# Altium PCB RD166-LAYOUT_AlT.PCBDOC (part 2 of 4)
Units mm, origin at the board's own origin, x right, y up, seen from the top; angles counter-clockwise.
Board outline 88.7 x 59.07 mm, 2 copper layers (TOP, BOTTOM), stack 0 mm thick; 138 components, 120 nets, 706 pads, 0 vias.
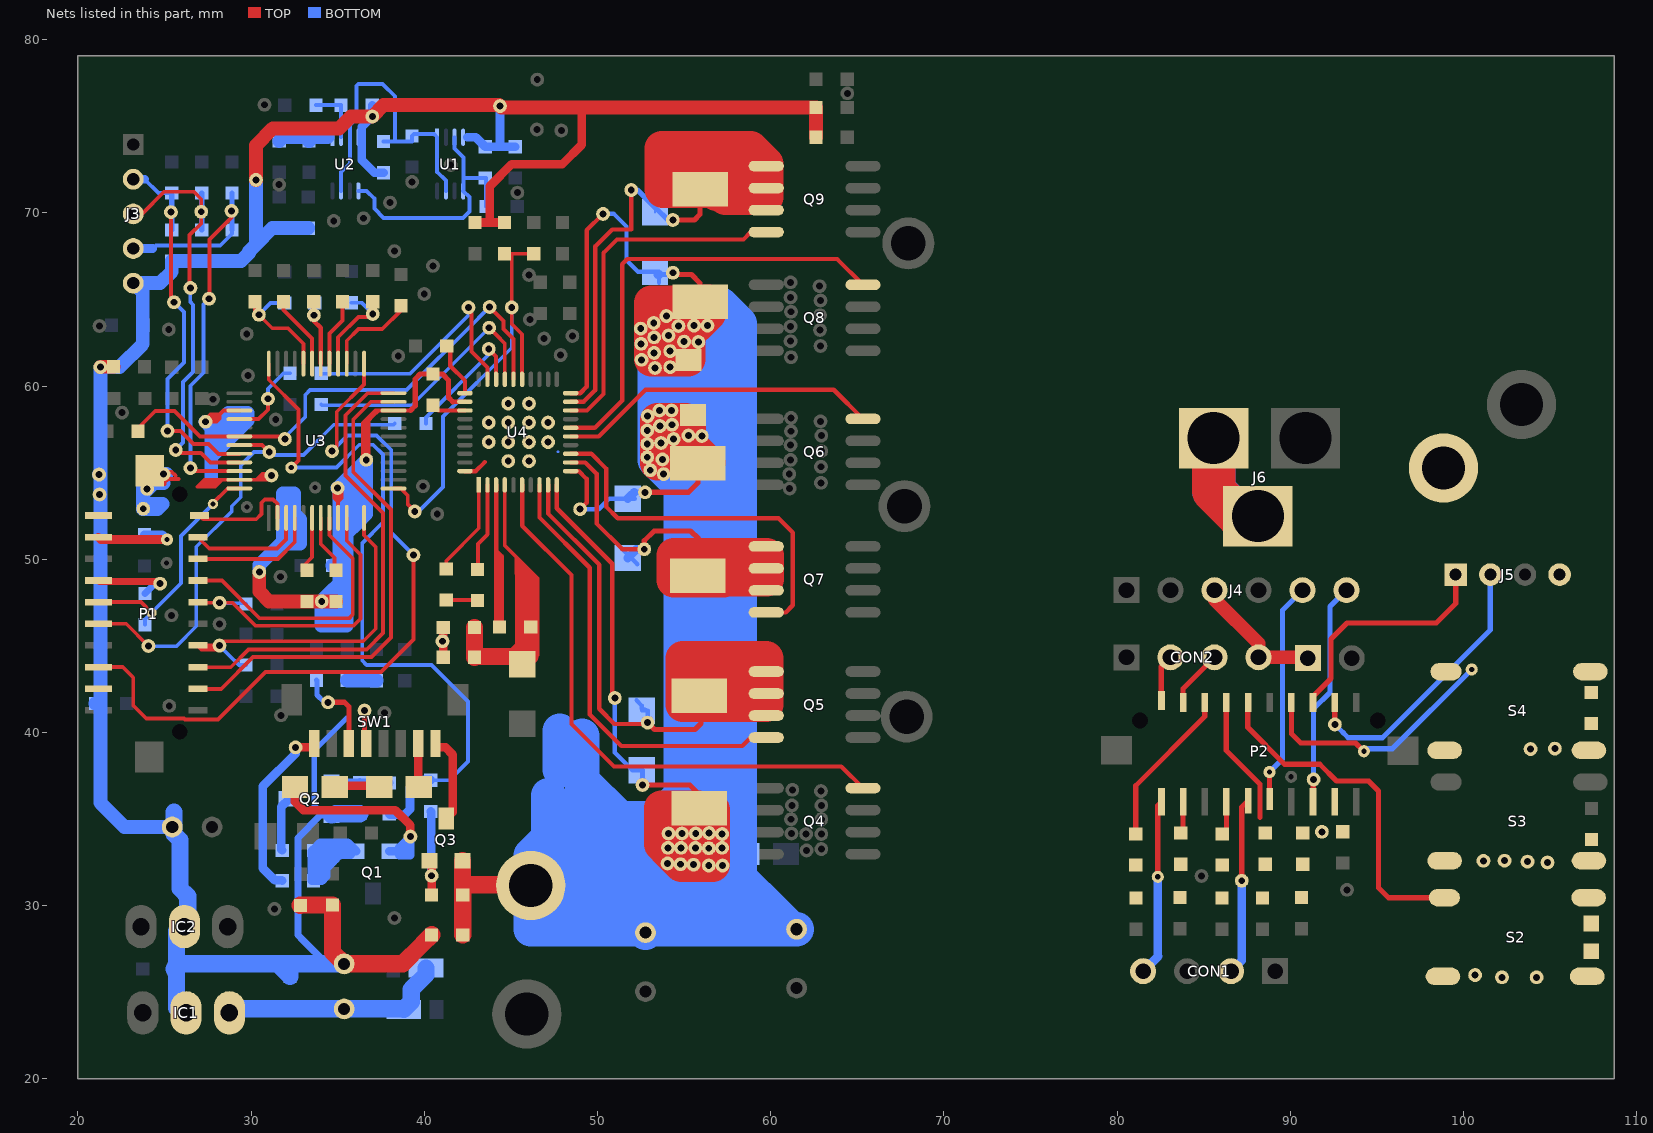
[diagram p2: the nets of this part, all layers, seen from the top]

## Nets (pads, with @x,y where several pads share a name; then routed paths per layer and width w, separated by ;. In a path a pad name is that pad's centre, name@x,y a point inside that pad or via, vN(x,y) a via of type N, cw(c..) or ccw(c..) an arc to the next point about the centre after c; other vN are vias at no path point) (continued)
GND: C3.2 C4.2 C5.2 C6.2 C9.2 C10.2 C11.2 C12.2 C13.2 C14.1 C15.2 C16.1 C17.2 C18.2 C19.2 C20.2 C21.2 C23.2 C27.2 C28.2 C29.2 C30.2 C34.2 IC1.2 IC2.2 J3.5 NTC1.1 P1.10 P1.22 pad.@21.3,61.091 pad.@21.25,53.741 pad.@21.225,54.891 pad.@23.775,52.916 pad.@24,54.066 pad.@24.95,54.916 pad.@27.375,57.941 pad.@30.287,71.903 pad.@30.476,49.265 pad.@31.176,54.84 pad.@34.084,47.565 pad.@35,54.116 pad.@36.65,55.743 pad.@36.551,41.265 pad.@37,75.566 pad.@44.375,76.166 Q2.E R5.1 R9.2 R11.1 R15.1 R18.2 R20.2 SW1.4 U1.4 U2.4 U3.9 U3.22 U3.39 U3.47 U4.32 | length 281.5
  TOP w0.22: P1.22@24.651,54.34 25.001,54.34 ; P1.22@24.901,54.39 24.951,54.39 25.201,54.64 25.826,54.64 ; pad.@25.038,54.828 pad.@24.95,54.916 25.076,55.04 25.426,55.04 25.638,54.828 ; U3.47@29.325,54.591 28.326,54.59 ; U3.39@29.325,58.591 28.401,58.59 28.176,58.365 ; U3.47@29.326,54.59 30.301,54.59 ; pad.@35.001,54.115 pad.@35.026,54.115 ; U3.9@35.026,52.392 35.026,53.34 ; pad.@36.65,55.743 36.776,55.869 36.776,58.015 37.03,58.269 ; pad.@36.65,55.743 pad.@36.601,55.793 ; 37.352,58.591 U3.22@38.225,58.591 ; U3.22@38.225,58.591 39.201,58.59 ; 27.101,54.39 28.126,54.39 ; 27.101,54.39 26.901,54.19 27.926,54.19 28.126,54.39 ; 27.101,54.39 27.301,54.59 28.326,54.59 ; pad.@27.376,57.942 pad.@27.375,57.941 pad.@27.476,57.94 ; pad.@27.376,57.942 27.376,58.09 27.651,58.365 ; pad.@27.376,57.942 27.651,58.217 27.651,58.365 ; pad.@27.476,57.94 pad.@27.751,57.94 ; pad.@27.476,57.94 27.901,58.365 ; 27.651,58.365 27.901,58.365 ; pad.@27.751,57.94 28.176,58.365 ; pad.@27.751,57.94 28.001,57.94 28.176,58.115 28.176,58.365 ; 27.901,58.365 28.176,58.365 ; 28.126,54.39 28.326,54.59 ; 30.301,54.59 30.501,54.79 ; 30.301,54.59 pad.@30.926,54.59 ; 30.501,54.79 pad.@31.126,54.79 ; 30.501,54.79 30.651,54.94 31.076,54.94 pad.@31.176,54.84 pad.@31.126,54.79 ; pad.@30.926,54.59 pad.@31.126,54.79 ; pad.@30.926,54.59 pad.@31.126,54.79 ; 35.026,53.34 pad.@35.026,54.115 ; 35.026,53.34 34.826,53.54 34.826,53.915 pad.@35.026,54.115 ; 35.026,53.34 35.226,53.54 35.226,53.915 pad.@35.026,54.115 ; pad.@36.601,55.793 36.451,55.943 36.451,57.865 36.601,58.015 ; pad.@36.601,55.793 36.601,58.015 ; 36.601,58.015 37.176,58.59 37.351,58.59 ; 37.03,58.269 37.351,58.59 ; 37.03,58.269 37.351,58.59
  TOP w0.25: 41.65,59.091 U4.32@42.35,59.091
  TOP w0.3: pad.@36.551,41.265 36.551,39.465 SW1.4@36.65,39.366 ; 39.201,58.59 39.476,58.865 39.476,60.415 39.751,60.69 C34.2@40.5,60.691 ; C34.2@40.5,60.691 41.051,60.69 41.401,60.34 41.401,59.34 41.65,59.091
  TOP w0.5: C29.2@42.925,69.441 43.776,69.44 ; C30.2@44.625,69.441 43.776,69.44 ; 49.101,76.09 49.101,73.94 47.976,72.815 45.051,72.815 43.776,71.54 43.776,69.44
  TOP w0.8: pad.@21.3,61.091 21.325,61.116 R11.1@22.05,61.116 ; pad.@30.287,71.903 30.279,71.912 30.279,73.895 31.249,74.865 35.076,74.865 35.777,75.566 pad.@37,75.566 37.656,76.222 44.319,76.222 pad.@44.375,76.166 44.451,76.09 49.101,76.09 62.625,76.09 NTC1.1@62.625,74.366 ; pad.@30.476,49.265 30.476,48.132 31.042,47.566 C27.2@33.225,47.566 33.226,47.565 pad.@34.084,47.565 34.084,47.566 C28.2@34.9,47.566
  TOP w1: R15.1@32.85,30.016 32.875,30.041 C12.2@34.7,30.041 34.701,30.04 34.701,27.315 ; C3.2@35.376,26.64 38.751,26.64 39.872,27.761 ; 39.872,27.763 R9.2@40.425,28.316 ; 34.701,27.315 C3.2@35.375,26.641 ; 34.701,27.315 C3.2@35.375,26.641 ; 34.701,27.315 C3.2@35.375,26.641
  BOTTOM w0.127: 29.269,58.446 29.275,58.441
  BOTTOM w0.3: Q2.E@34.232,35.234 33.65,35.816 33.65,38.966 35.525,40.841
  BOTTOM w0.4: 33.012,28.004 34.375,26.641 ; Q2.E@34.649,35.234 34.232,35.234 34.018,35.234 32.7,33.916 32.7,28.316 33.012,28.004 34.375,26.641 ; C3.2@35.375,26.916 C3.2@35.375,26.641 34.375,26.641
  BOTTOM w0.5: R20.2@37,76.216 pad.@37,75.566 36.4,74.966 36.4,73.041 37.125,72.316 C15.2@37.65,72.316 ; 42.476,74.366 42.975,74.366 R18.2@43.525,73.816 44.375,73.816 ; pad.@44.375,76.166 44.375,73.816 ; C14.1@45.25,73.816 44.375,73.816
  BOTTOM w0.8: C9.2@21.025,41.666 21.027,41.664 C9.2@21.3,41.664 ; pad.@21.25,54.866 pad.@21.225,54.891 pad.@21.3,54.966 ; pad.@24,54.066 pad.@24.038,54.028 ; 24.95,54.391 24.4,54.391 pad.@24.038,54.028 ; pad.@25.125,54.916 23.75,54.916 23.75,53.741 ; C6.2@25.45,34.541 22.7,34.541 21.3,35.941 C9.2@21.3,41.664 ; pad.@27.375,57.941 27.7,57.616 ; 27.7,54.641 27.7,55.916 ; pad.@30.287,71.903 30.287,68.178 ; pad.@30.476,49.265 30.475,49.666 31.725,50.916 32.325,50.916 ; 31.85,51.041 31.85,53.791 32.475,53.791 32.475,52.651 32.825,52.301 32.825,50.916 32.325,50.916 ; 32.325,52.501 32.325,50.916 ; C16.1@33.3,69.116 C17.2@31.625,69.116 31.225,69.116 30.287,68.178 ; 34.775,48.091 34.775,46.166 ; 35.515,54.351 35.515,51.481 ; C11.2@35.55,43.016 35.575,42.991 C10.2@37.25,42.991 ; 36.137,54.903 36.137,52.103 ; C9.2@21.3,41.664 21.3,54.891 pad.@21.3,54.966 ; pad.@21.3,54.966 pad.@21.3,61.091 22.4,61.091 23.75,62.441 C18.2@23.75,63.516 23.75,63.518 23.75,65.391 ; J3.5@23.74,65.941 24.75,65.941 25.425,66.616 C21.2@25.425,67.216 C20.2@27.15,67.216 C19.2@28.9,67.216 29.425,67.216 29.881,67.672 29.881,67.772 30.287,68.178 ; J3.5@23.74,65.941 J3.5@23.2,65.941 23.75,65.391 ; J3.5@23.74,65.941 23.75,65.931 23.75,65.391 ; pad.@23.75,52.891 23.75,53.741 ; pad.@23.75,52.891 24.6,52.891 24.9,53.191 24.05,53.191 pad.@23.775,52.916 pad.@23.75,52.891 ; 23.75,53.741 pad.@24.038,54.028 ; 27.7,55.916 27.7,56.866 ; 27.7,55.916 29.8,58.016 29.8,58.441 29.275,58.441 ; 27.7,56.866 27.7,57.616 ; 27.7,56.866 29.275,58.441 ; 27.7,57.616 27.875,57.616 28.7,58.441 29.275,58.441 ; pad.@34.05,47.532 34.05,47.566 34.066,47.582 34.525,48.041 ; pad.@34.05,47.532 34.05,46.176 34.06,46.166 34.775,46.166 ; pad.@34.05,47.532 pad.@34.084,47.565 34.525,48.007 34.525,48.041 ; 34.525,48.041 35.093,48.609 35.093,49.641 35.093,54.023 35,54.116 35.022,54.116 pad.@36.65,55.743 36.65,52.616 36.137,52.103 ; 34.775,46.166 35.515,46.166 35.515,51.481 ; 35.515,51.481 36.137,52.103
  BOTTOM w0.801: C23.2@34.7,49.641 35.093,49.641
  BOTTOM w1: C6.2@25.45,34.541 C6.2@25.55,34.541 ; C5.2@25.55,26.342 C5.2@25.55,26.341 C5.2@25.7,26.491 ; 25.55,35.391 C6.2@25.55,34.541 ; IC2.2@26.15,28.791 IC2.2@26.375,29.216 ; IC1.2@26.25,23.816 26.025,23.766 25.7,24.091 C5.2@25.7,26.491 ; 31.675,26.491 C4.2@32.249,25.917 ; C4.2@32.249,25.916 C4.2@32.249,25.917 ; C4.2@32.25,25.916 C4.2@32.249,25.917 ; Q2.E@34.65,35.234 34.897,35.316 R5.1@36.275,35.316 ; C3.2@35.375,26.641 34.375,26.641 32.249,26.641 ; C6.2@25.55,34.541 25.55,34.141 25.9,33.791 25.9,30.991 26.35,30.541 26.35,29.241 IC2.2@26.375,29.216 ; C5.2@25.7,26.491 25.7,28.541 26.05,28.891 IC2.2@26.375,29.216 ; C5.2@25.7,26.491 25.85,26.641 32.249,26.641 ; C4.2@32.249,25.917 32.249,26.641
GND1: BOOT1.1 C43.1 C44.2 C45.2 C46.2 CON1.4 CON2.4 J4.3 J5.4 P2.10 pad.@82.351,31.665 pad.@91.823,34.266 pad.@100.675,25.991 pad.@101.15,32.591 pad.@102.225,25.866 pad.@102.375,32.598 pad.@103.7,32.541 pad.@103.875,39.041 pad.@104.85,32.491 pad.@104.225,25.866 pad.@105.275,39.066 R51.2 S2.2 S2.3 S3.2 S3.3 S4.2 S4.3 | length 18
  TOP w0.3: pad.@82.351,31.665 82.351,35.789 P2.10@82.565,36.003
  TOP w0.8: J4.3@85.626,48.215 85.626,47.69 88.166,45.15 CON2.4@88.165,44.341 90.961,44.34 BOOT1.1@91.01,44.291
  BOTTOM w0.5: CON1.4@81.505,26.216 82.375,27.086 82.351,27.11 pad.@82.351,31.665
HU: C21.1 J3.2 pad.@25.55,64.841 pad.@25.176,57.415 pad.@25.375,70.041 R26.1 U3.44 | length 22.8
  TOP w0.23: pad.@25.176,57.415 25.926,57.415 26.676,56.665 27.551,56.665 28.126,56.09 U3.44@29.325,56.091 ; 25.375,68.689 pad.@25.375,70.041 ; 25.376,68.688 25.376,65.015 pad.@25.55,64.841
  BOTTOM w0.23: 23.85,71.941 24.65,71.141 R26.1@25.425,71.141 ; pad.@25.175,57.416 25.175,60.416 26.125,61.366 26.125,64.266 pad.@25.55,64.841
  BOTTOM w0.3: pad.@25.375,70.041 pad.@25.425,70.041 ; C21.1@25.425,69.016 pad.@25.425,70.041 ; R26.1@25.425,71.141 pad.@25.425,70.041
  BOTTOM w0.5: J3.2@23.2,71.941 23.85,71.941
HV: C20.1 J3.3 pad.@25.651,56.315 pad.@26.5,65.666 pad.@27.125,70.066 R25.1 U3.45 | length 26.1
  TOP w0.22: J3.3@23.2,69.941 23.701,69.94 24.976,71.215 26.701,71.215 27.126,70.79 pad.@27.125,70.066 27.126,69.39 26.451,68.715 26.451,65.666 pad.@26.5,65.666 ; pad.@25.651,56.315 25.826,56.14 27.101,56.14 27.651,55.59 U3.45@29.325,55.591 ; pad.@26.451,65.665 pad.@26.5,65.666
  BOTTOM w0.22: pad.@25.651,56.315 26.08,56.744 26.08,60.235 26.65,60.805 26.65,64.691 26.495,64.846 26.495,65.661 pad.@26.5,65.666
  BOTTOM w0.3: C20.1@27.15,69.016 27.15,70.041 pad.@27.125,70.066 27.15,70.091 R25.1@27.15,71.141
HW: C19.1 J3.4 pad.@26.501,55.265 pad.@27.575,65.041 pad.@28.875,70.116 R24.1 U3.46 | length 27.3
  TOP w0.22: pad.@26.501,55.265 26.501,55.09 28.337,55.09 ; pad.@27.575,65.041 27.601,65.041 27.601,68.465 28.875,69.739 pad.@28.875,70.116 ; 28.338,55.091 U3.46@29.325,55.091
  BOTTOM w0.22: 24.325,67.941 24.5,68.116 28.225,68.116 28.9,68.791 C19.1@28.9,69.016 ; pad.@26.501,55.265 26.5,60.016 27.25,60.766 27.25,64.716 pad.@27.575,65.041
  BOTTOM w0.3: pad.@28.875,70.116 pad.@28.9,70.116 ; C19.1@28.9,69.016 pad.@28.9,70.116 ; R24.1@28.9,71.141 pad.@28.9,70.116
  BOTTOM w0.5: J3.4@23.2,67.941 24.325,67.941
K-UP: P1.16 pad.@28.176,47.49 R37.1 U3.10 | length 17.9
  TOP w0.22: P1.16@26.925,47.526 26.961,47.49 pad.@28.176,47.49 28.926,47.49 30.256,46.16 35.921,46.16 36.326,46.565 36.326,50.265 35.526,51.065 U3.10@35.525,52.391
  BOTTOM w0.22: pad.@28.15,47.466 pad.@28.2,47.466 ; pad.@28.176,47.49 pad.@28.2,47.466 ; R37.1@29.7,47.416 29.65,47.466 pad.@28.2,47.466
K-UP1: C44.1 P2.16 S2.1 S2.4 | length 20.1
  TOP w0.3: P2.16@87.565,41.741 87.551,41.727 87.551,40.29 89.676,38.165 91.701,38.165 92.676,37.19 94.526,37.19 95.101,36.615 95.101,31.04 95.681,30.46 S2.1@98.896,30.46
LED2: P1.17 U3.8 | length 16.1
  TOP w0.22: P1.17@26.925,48.776 28.315,48.776 30.501,46.59 35.651,46.59 35.876,46.815 35.876,50.04 34.526,51.39 U3.8@34.525,52.391
LED3: P1.7 pad.@24.751,48.59 R27.1 | length 4.8
  TOP w0.4: P1.7@21.187,48.776 21.248,48.715 24.626,48.715 pad.@24.751,48.59
  BOTTOM w0.4: R27.1@23.875,48.016 24.45,48.591 pad.@24.751,48.59
LED4: P1.9 pad.@25.151,51.14 R28.1 | length 5.4
  TOP w0.5: P1.9@21.187,51.276 21.323,51.14 pad.@25.151,51.14
  BOTTOM w0.5: R28.1@23.85,51.416 24.875,51.416 pad.@25.151,51.14
LED5: P1.18 U3.4 | length 7.4
  TOP w0.22: P1.18@26.925,50.026 26.936,50.015 31.551,50.015 32.526,50.99 U3.4@32.525,52.391
LED+: R3.2 SW1.7 | length 2.5
  TOP w0.5: SW1.7@39.65,39.366 39.651,39.365 39.651,36.883 R3.2@39.693,36.841
LED-: Q3.C SW1.8 | length 5.3
  TOP w0.5: SW1.8@40.65,39.366 40.65,39.14 41.226,39.14 41.651,38.715 41.651,35.407 Q3.C@41.265,35.021
LEDB: P2.17 R52.2 | length 7.5
  TOP w0.3: P2.17@86.315,41.741 86.301,41.727 86.301,38.965 88.251,37.015 88.251,35.719 ; 88.25,35.091 88.25,35.718
LEDC: P2.7 R53.2 | length 2
  TOP w0.3: R53.2@86.075,34.141 86.315,34.381 P2.7@86.315,36.003
LEDD: P2.9 R54.2 | length 1.9
  TOP w0.3: R54.2@83.675,34.191 83.801,34.317 83.801,35.989 P2.9@83.815,36.003
LEDE: P2.18 R55.2 | length 9.3
  TOP w0.3: R55.2@81.075,34.141 81.075,35.214 ; 81.076,35.215 81.076,36.925 85.065,40.914 P2.18@85.065,41.741
N02078: C3.1 C4.1 D1.1 D2.1 IC1.1 | length 13.2
  BOTTOM w0.8: C4.1@32.25,24.116 32.264,24.102 C4.1@32.264,24.041
  BOTTOM w1: IC1.1@28.75,23.816 28.975,24.041 32.264,24.041 C3.1@35.375,24.041 D2.1@38.789,24.041 ; D2.1@38.814,24.016 D2.1@38.789,24.041 ; D2.1@38.814,24.016 D2.1@38.815,24.041 ; D1.1@40.1,26.391 40.1,26.016 39.25,25.166 39.25,24.452 38.839,24.041 D2.1@38.815,24.041 ; D2.1@38.789,24.041 D2.1@38.815,24.041
N02082: pad.@40.426,31.726 Q3.B R7.2 R8.1 | length 5.8
  TOP w0.5: Q3.B@40.307,32.591 40.426,32.472 pad.@40.426,31.726 pad.@40.426,31.375 ; R8.1@40.425,30.616 pad.@40.425,31.374
  BOTTOM w0.5: R7.2@40.375,35.441 40.4,35.416 40.4,31.752 pad.@40.426,31.726
N02094: Q2.C R6.2 | length 3.2
  BOTTOM w0.5: R6.2@31.8,33.191 31.75,33.241 31.75,35.705 Q2.C@32.22,36.175
N02110: Q2.B R1.1 R5.2 | length 3.5
  BOTTOM w0.5: R1.1@37.975,37.091 36.3,37.091 R5.2@36.275,37.116 ; Q2.B@34.722,37.091 Q2.B@34.65,37.133 34.693,37.091 Q2.B@34.722,37.091 ; Q2.B@34.722,37.091 R5.2@36.25,37.091 ; R5.2@36.25,37.091 R5.2@36.275,37.116 ; R5.2@36.25,37.091 36.275,37.091 R5.2@36.275,37.116
N02126: Q1.B R4.1 R6.1 | length 17.7
  BOTTOM w0.127: R4.1@33.6,31.441 33.6,32.691 33.6,33.141 R6.1@33.6,33.191 33.65,33.141 33.652,33.139 35.323,33.139 Q1.B@36.084,33.139
  BOTTOM w0.5: R4.1@33.6,31.441 33.5,31.441 33.5,32.691 ; R4.1@33.6,31.441 34.075,31.441 34.35,31.716 34.35,32.166 34.775,32.591 ; R6.1@33.6,33.191 R6.1@33.6,33.141 ; R4.1@33.875,31.716 33.875,32.691 ; 34.2,32.316 34.2,32.691 ; 35.05,32.941 35.125,32.941 ; Q1.B@35.75,32.941 35.125,32.941 ; Q1.B@36.084,33.139 35.582,33.641 35.525,33.641 ; 33.5,32.691 33.6,32.691 33.875,32.691 ; 33.5,32.691 R6.1@33.5,33.141 ; R6.1@33.5,33.141 33.575,33.216 34,33.641 35.525,33.641 ; R6.1@33.5,33.141 R6.1@33.6,33.141 ; R6.1@33.6,33.141 33.65,33.141 35.325,33.141 ; 33.875,32.691 34.2,32.691 ; 34.2,32.691 34.875,32.691 35.125,32.941 ; 35.125,32.941 35.323,33.139 35.325,33.141 ; 35.325,33.141 35.575,33.141 35.575,33.591 35.525,33.641
N06909: C15.1 R19.2 U1.1 U1.7 U2.3 U2.7 | length 18.5
  BOTTOM w0.23: U2.7@35.2,71.266 35.2,72.366 35.7,72.866 U2.3@35.7,74.366 35.7,75.066 36.075,75.441 36.075,77.316 36.2,77.441 37.6,77.441 38.325,76.716 38.325,74.116 ; C15.1@37.65,74.116 38.325,74.116 ; U1.7@41.25,71.266 41.25,71.866 40.75,72.366 U1.1@40.75,74.366 40.575,74.541 39.4,74.541 R19.2@39.3,74.441 39.3,74.116 38.325,74.116
N06913: R17.1 R18.1 U1.3 U1.5 U2.5 | length 15.1
  BOTTOM w0.23: U2.5@36.2,71.266 36.675,71.266 37.125,70.816 37.125,70.241 37.65,69.716 42.225,69.716 42.6,70.091 42.6,70.916 U1.5@42.25,71.266 42.275,71.291 42.275,72.016 ; U1.3@41.75,74.366 41.75,73.716 42.275,73.191 42.275,72.016 ; R17.1@43.575,70.366 43.575,72.016 R18.1@43.525,72.016 42.275,72.016
N06957: R20.1 R21.2 U2.2 | length 3.3
  BOTTOM w0.23: R21.2@33.75,76.216 R20.1@35.2,76.216 ; U2.2@35.2,74.366 R20.1@35.2,76.216
N23263: C26.1 pad.@37.025,64.166 R31.1 U3.28 | length 6.3
  TOP w0.22: U3.28@35.026,61.292 35.026,62.815 36.201,63.99 36.849,63.99 pad.@37.025,64.166 C26.1@37.025,64.866
  BOTTOM w0.22: R31.1@35.8,64.816 36.375,64.816 37,64.191 pad.@37.025,64.166
N23267: C25.1 pad.@30.45,64.116 R29.2 U3.32 | length 7
  TOP w0.22: C25.1@30.225,64.866 30.225,64.341 pad.@30.45,64.116 30.997,63.569 31.226,63.34 32.126,63.34 33.026,62.44 U3.32@33.026,61.292
  BOTTOM w0.22: pad.@30.45,64.116 31.125,64.791 R29.2@31.95,64.791
N23275: P1.2
N23279: C24.1 pad.@33.625,64.091 R30.1 U3.30 | length 4.5
  TOP w0.25: pad.@33.625,64.091 C24.1@33.625,64.866 ; pad.@33.626,64.09 33.626,63.765 34.026,63.365 U3.30@34.026,61.292
  BOTTOM w0.25: pad.@33.625,64.091 33.625,64.741 R30.1@33.675,64.791
N026301: R2.2 R3.1 | length 2.6
  TOP w0.5: R2.2@34.825,36.841 34.899,36.915 37.333,36.915 R3.1@37.407,36.841
N29992: LED4.K R54.1
N30008: LED3.K R53.1
N30012: LED2.K R52.1
N30064: LED5.K R55.1
N30078: P2.2
N36723: C37.2 pad.@51.951,71.315 pad.@54.35,69.591 Q9.1 Q9.2 Q9.3 R48.1 U4.19 | length 50.6
  TOP w0.127: R48.1@55.925,71.366 R48.1@57.375,71.366
  TOP w0.25: U4.19@48.45,59.091 49.201,59.09 49.876,59.765 49.876,68.065 50.851,69.04 51.951,69.04 pad.@51.951,71.315 ; 53.986,70.865 55.426,70.865 55.851,71.29 R48.1@55.925,71.366
  TOP w0.3: pad.@54.35,69.591 55.601,69.59 55.926,69.915 R48.1@55.926,71.29 ; 58.601,70.162 Q9.3@59.743,70.163 Q9.3@59.744,70.164
  TOP w0.5: R48.1@55.926,71.29 R48.1@55.925,71.366
  TOP w2: 54.926,72.59 57.376,72.59 ; R48.1@56.851,71.115 56.676,71.29 55.926,71.29 55.851,71.29 53.776,71.29 53.704,71.362 53.704,73.718 58.855,73.718 59.744,72.829 Q9.2@59.743,71.433 ; 57.376,73.546 57.376,72.59 ; 57.826,71.365 R48.1@57.376,71.365 ; 59.202,73.371 59.202,70.89 ; 59.751,70.915 Q9.2@59.743,71.433 ; R48.1@57.376,71.365 57.376,72.59 ; R48.1@57.376,71.365 57.376,70.89 59.202,70.89 ; 59.202,70.89 Q9.2@59.743,71.433
  BOTTOM w0.127: C37.2@53.323,70.298 53.325,70.296 C37.2@53.325,70.031
  BOTTOM w0.3: pad.@51.951,71.315 52.305,71.316 53.323,70.298 53.358,70.298 54.065,69.591 pad.@54.35,69.591
N36737: C31.1 C32.1 C35.1 R40.1 U4.4 | length 51.3
  TOP w0.127: R40.1@45.65,43.945 45.65,44.09 45.67,44.11 R40.1@45.951,44.39
  TOP w0.22: 44.651,44.39 45.351,45.09 ; U4.4@44.65,54.291 44.651,50.79 45.326,50.115 ; 45.351,49.115 45.351,45.09 ; 45.751,48.751 45.751,48.74 ; 45.951,48.49 C35.1@45.951,46.09 ; 46.151,44.805 46.151,44.855 ; 46.151,48.29 C35.1@46.151,46.09 ; 46.551,44.455 46.551,48.89 45.326,50.115 ; 45.326,49.365 45.326,49.615 ; 45.326,49.365 45.326,49.165 45.551,48.94 ; 45.326,49.365 45.976,48.715 45.976,48.515 ; 45.326,49.615 45.326,49.89 ; 45.326,49.615 46.176,48.765 46.176,48.315 45.976,48.515 ; 45.326,49.89 46.351,48.865 46.351,44.655 46.151,44.855 ; 45.326,49.89 45.326,50.115 ; 45.351,45.09 45.551,45.29 ; 45.351,45.09 45.351,44.59 45.551,44.39 45.551,45.29 ; 45.551,45.29 45.551,48.94 ; 45.551,48.94 45.751,48.74 ; 45.751,46.09 45.751,48.74 ; 45.751,46.09 C35.1@45.951,46.09 ; 45.751,46.09 45.751,44.79 45.704,44.39 45.67,44.11 45.651,43.945 45.951,44.244 45.951,44.39 45.951,45.055 ; 45.751,48.74 45.976,48.515 ; 45.951,45.055 C35.1@45.951,46.09 ; 45.951,45.055 46.151,44.855 ; C35.1@45.951,46.09 C35.1@46.151,46.09 ; 46.151,44.855 C35.1@46.151,46.09
  TOP w1: C32.1@42.9,46.066 C31.1@42.9,44.341 42.949,44.39 44.651,44.39 45.551,44.39 45.704,44.39 45.951,44.39 R40.1@46.086,44.39
N36741: C35.2 U4.3 | length 17.8
  TOP w0.127: 44.151,46.947 44.35,46.748 C35.2@44.35,46.091
  TOP w0.25: U4.3@44.15,54.291 44.15,50.691 44.151,50.49 ; C35.2@44.35,46.091 44.151,46.29 44.151,46.947 44.151,50.49 ; 44.351,50.14 C35.2@44.35,46.091 C35.2@44.426,46.165 ; C35.2@44.476,46.24 44.476,50.165 44.151,50.49
N36745: C33.2 U4.1 | length 5.6
  TOP w0.22: C33.2@41.275,49.441 41.275,49.915 43.151,51.79 U4.1@43.15,54.291
N36749: C34.1 U4.33 | length 2
  TOP w0.25: C34.1@40.5,58.891 40.801,58.59 U4.33@42.35,58.591
N36761: C33.1 R46.1 | length 1.8
  TOP w0.22: C33.1@41.275,47.641 43.051,47.64 R46.1@43.075,47.616
N36787: C42.2 pad.@52.9,40.566 Q5.1 Q5.2 Q5.3 R50.1 U4.9 | length 49.8
  TOP w0.25: 47.15,53.391 U4.9@47.15,54.291 ; 47.151,53.39 47.151,52.64 50.101,49.69 50.101,41.365 50.976,40.49 52.824,40.49 pad.@52.9,40.566 ; R50.1@54.918,42.115 R50.1@55.875,42.116 ; R50.1@54.918,42.565 55.426,42.565 R50.1@55.875,42.116 55.976,42.015 R50.1@55.976,41.615
  TOP w0.3: pad.@52.9,40.566 53.301,40.165 55.626,40.165 55.976,40.515 R50.1@55.976,41.615
  TOP w1: R50.1@54.718,41.415 R50.1@54.918,41.615
  TOP w2: 54.918,43.165 55.526,43.165 55.751,43.39 57.397,43.39 ; 54.918,43.165 54.918,42.565 54.918,42.115 54.918,41.615 55.976,41.615 R50.1@57.397,41.615 ; 54.918,43.165 54.918,44.29 57.397,44.29 ; R50.1@57.397,41.615 57.397,43.39 ; R50.1@57.397,41.615 58.651,41.615 ; 57.397,43.39 57.397,44.29 ; 57.397,44.29 58.651,44.29 ; 58.651,41.615 58.651,44.29 ; 58.651,41.615 59.744,41.615 59.744,44.29 58.651,44.29
  BOTTOM w0.2: C42.2@52.556,41.391 52.55,41.386 C42.2@52.55,41.256 52.881,41.256 C42.2@52.884,41.259
  BOTTOM w0.25: C42.2@52.25,41.855 52.55,41.555 52.549,41.407 52.556,41.391 52.598,41.374 52.884,41.259 52.9,41.266 pad.@52.9,40.566 pad.@52.9,40.555
N36791: Q7.4 U4.13 | length 21.9
  TOP w0.25: U4.13@48.45,56.091 49.651,56.09 50.501,55.24 50.501,53.04 51.176,52.365 60.451,52.365 61.276,51.54 61.276,47.34 60.866,46.93 Q7.4@59.744,46.93
N36795: C41.2 pad.@52.701,50.578 Q7.1 Q7.2 Q7.3 R49.1 U4.12 | length 39.8
  TOP w0.25: U4.12@48.45,55.591 49.301,55.59 49.951,54.94 49.951,52.065 51.438,50.578 pad.@52.701,50.578 ; 54.001,50.39 54.401,49.99 54.601,49.79 R49.1@55.251,49.14 ; R49.1@54.401,49.14 R49.1@55.251,49.14 ; R49.1@55.951,49.14 55.826,49.14 R49.1@55.251,49.14
  TOP w0.3: pad.@52.701,50.578 52.701,51.065 53.276,51.64 55.376,51.64 55.826,51.19 55.826,50.24
  TOP w0.5: R49.1@55.751,48.79 55.826,48.865 R49.1@55.826,49.04 ; R49.1@55.8,49.041 R49.1@55.826,49.04 ; 55.826,50.24 55.826,49.89 55.826,49.14 R49.1@55.826,49.04
  TOP w2: 58.451,50.065 58.451,49.965 58.376,49.89 ; Q7.2@59.743,49.471 Q7.2@59.776,49.471 ; R49.1@54.401,49.59 54.401,49.99 54.401,50.24 55.826,50.24 59.776,50.24 Q7.2@59.776,49.471 ; R49.1@54.401,49.59 54.601,49.79 54.701,49.89 55.826,49.89 58.376,49.89 ; R49.1@54.401,49.59 54.401,49.14 54.401,48.79 55.751,48.79 57.276,48.79 R49.1@57.326,48.84 ; R49.1@57.326,48.84 59.776,48.84 Q7.2@59.776,49.471 ; R49.1@57.326,48.84 58.376,49.89
  BOTTOM w0.25: C41.2@51.425,50.591 C41.2@51.845,50.171 ; C41.2@51.751,50.074 51.841,50.168 C41.2@51.845,50.171 ; C41.2@52.304,49.712 C41.2@51.845,50.171
  BOTTOM w0.3: C41.2@52.252,50.578 pad.@52.701,50.578
  BOTTOM w0.5: C41.2@51.75,50.075 C41.2@51.75,50.075 51.841,50.168 51.845,50.171 C41.2@52.252,50.578
N36811: Q4.4 U4.6 | length 33.3
  TOP w0.25: U4.6@45.651,54.29 45.651,51.94 48.501,49.09 48.501,40.49 50.951,38.04 64.079,38.04 Q4.4@65.331,36.788
N36815: Q5.4 U4.8 | length 25.6
  TOP w0.25: U4.8@46.65,54.291 46.651,52.415 49.551,49.515 49.551,41.04 51.376,39.215 58.362,39.215 58.855,39.708 Q5.4@59.743,39.709
N36819: Q6.4 U4.15 | length 18.7
  TOP w0.25: U4.15@48.451,57.09 50.076,57.09 52.776,59.79 63.642,59.79 Q6.4@65.331,58.101
N36823: Q9.4 U4.18 | length 20.3
  TOP w0.25: U4.18@48.45,58.591 49.401,58.59 50.351,59.54 50.351,67.69 51.126,68.465 58.428,68.465 58.855,68.892 Q9.4@59.743,68.893
N36827: Q8.4 U4.16 | length 26.2
  TOP w0.25: U4.16@48.451,57.59 49.851,57.59 51.426,59.165 51.426,67.04 51.726,67.34 63.836,67.34 Q8.4@65.331,65.845
N36835: R46.2 U4.2 | length 5.1
  TOP w0.22: R46.2@43.075,49.416 43.101,49.441 43.101,50.89 43.651,51.44 U4.2@43.65,54.291
N36895: R47.2 U4.31 | length 3.3
  TOP w0.127: R47.2@41.3,62.316 41.499,62.316 R47.2@41.501,62.314
  TOP w0.25: R47.2@41.501,62.314 41.501,61.165 42.351,60.315 42.351,59.969 42.35,59.968 U4.31@42.35,59.591
N88880: R22.1 R23.2 U2.1 | length 3.1
  BOTTOM w0.8: R23.2@31.625,74.141 31.85,74.366 R22.1@33.355,74.366 ; R22.1@33.35,74.141 R22.1@33.355,74.366 ; 34.409,74.366 R22.1@33.355,74.366
N172117: LED1.K R51.1
N375834: pad.@42.551,64.54 R44.2 U4.29 | length 15
  TOP w0.22: pad.@42.551,64.54 42.451,64.44 42.726,64.165 42.726,61.99 43.651,61.065 U4.29@43.65,60.391
  BOTTOM w0.22: R44.2@34.05,60.741 34.075,60.716 39.175,60.716 42.55,64.091 pad.@42.55,64.54
N2368926: R34.2 U3.27 | length 5.5
  TOP w0.22: U3.27@35.526,61.292 35.526,62.615 36.201,63.29 37.576,63.29 38.651,64.365 R34.2@38.65,64.641 R34.2@38.65,64.641
N2368928: R33.2 U3.29 | length 3.9
  TOP w0.22: U3.29@34.526,61.292 34.526,63.04 35.276,63.79 R33.2@35.275,64.866
N2368930: R32.2 U3.31 | length 4.3
  TOP w0.22: R32.2@31.875,64.866 31.876,64.39 33.526,62.74 U3.31@33.526,61.292
N3758319: pad.@43.75,63.366 R45.2 U4.27 | length 14.9
  TOP w0.22: pad.@43.75,63.366 44.201,62.915 44.651,62.465 U4.27@44.65,60.391
  BOTTOM w0.22: R45.2@34.05,58.941 34.1,58.891 39.275,58.891 pad.@43.75,63.366
N3758320: pad.@43.725,62.141 R43.2 U4.28 | length 7.7
  TOP w0.22: pad.@43.725,62.141 44.151,61.715 44.151,61.241 U4.28@44.15,60.391
  BOTTOM w0.22: R43.2@40.1,57.841 40.1,58.191 43.603,61.694 43.725,61.816 pad.@43.725,62.141
NFAULT: C30.1 pad.@39.451,52.765 pad.@45.05,64.541 R41.1 U3.13 U4.25 | length 25.5
  TOP w0.22: U3.13@38.225,54.091 38.65,54.091 39.051,53.69 39.051,53.165 39.117,53.099 pad.@39.451,52.765 ; C30.1@44.625,67.641 45.051,67.641 ; pad.@45.05,64.541 pad.@45.051,64.54 ; U4.25@45.651,60.392 45.651,62.99 45.051,63.59 pad.@45.051,64.54 ; R41.1@46.325,67.641 45.051,67.641 ; pad.@45.051,64.54 45.051,67.641
  BOTTOM w0.22: pad.@39.451,52.765 39.675,52.766 41.075,54.166 41.075,58.241 45.05,62.216 pad.@45.05,64.541
NRESET: P1.14 pad.@28.176,45.015 R35.1 U3.12 | length 21.5
  TOP w0.22: P1.14@26.925,45.026 26.936,45.015 P1.14@26.951,45.015 ; pad.@28.176,44.79 27.126,44.79 26.926,44.99 26.943,45.008 P1.14@26.951,45.015 ; U3.12@36.525,52.391 36.526,51.39 37.201,50.715 37.201,45.99 36.476,45.265 28.426,45.265 pad.@28.176,45.015 P1.14@26.951,45.015
  BOTTOM w0.22: 28.738,44.453 pad.@28.176,45.015 28.738,44.453 29.3,43.891 R35.1@29.7,43.891
NRESET1: C46.1 P2.14 pad.@94.25,38.916 pad.@100.475,43.641 S4.1 S4.4 | length 14.6
  TOP w0.3: P2.14@90.065,41.741 90.065,39.926 90.601,39.39 93.775,39.39 pad.@94.25,38.916
  BOTTOM w0.3: pad.@94.25,38.916 94.4,39.066 95.9,39.066 pad.@100.475,43.641
PDELAY: pad.@32.325,55.291 R1.2 R7.1 U3.36 | length 42.5
  TOP w0.22: U3.36@31.025,61.291 31.026,60.365 32.74,58.651 32.74,55.706 pad.@32.325,55.291
  BOTTOM w0.22: pad.@32.325,55.291 33.005,55.291 34.925,55.291 36.25,56.616 37.05,56.616 37.625,56.041 37.625,52.141 36.425,50.941 36.425,44.141 36.675,43.891 40.425,43.891 42.525,41.791 42.525,38.316 41.45,37.241 R7.1@40.375,37.241 R7.1@40.375,37.241
  BOTTOM w0.5: R1.2@37.975,35.291 38.025,35.241 38.85,35.241 39.175,35.566 39.175,36.791 39.65,37.266 40.375,37.266 R7.1@40.375,37.241
PGND: C1.2 C2.2 C31.2 C32.2 C37.1 C38.1 C39.2 C40.2 C41.1 C42.1 pad.@41.05,45.266 pad.@43.725,56.766 pad.@43.725,57.891 pad.@44.85,55.666 pad.@44.85,56.766 pad.@44.85,57.891 pad.@44.85,58.991 pad.@46.05,55.666 pad.@46.05,56.766 pad.@46.05,57.891 pad.@46.05,58.991 pad.@46.15,31.166 pad.@47.15,56.766 pad.@47.15,57.891 pad.@49.001,52.89 pad.@50.325,69.941 pad.@51.001,41.99 pad.@52.5,63.316 pad.@52.6,36.966 pad.@52.9,58.266 pad.@52.55,61.516 pad.@52.75,53.866 pad.@52.525,62.441 pad.@52.875,55.891 pad.@52.875,56.666 pad.@52.875,57.441 pad.@53.05,55.141 pad.@53.6,57.691 pad.@53.25,63.641 pad.@53.75,55.766 pad.@53.275,61.916 pad.@53.275,62.816 pad.@53.325,61.041 pad.@53.575,58.591 pad.@53.675,56.716 pad.@53.825,54.916 pad.@53.975,64.041 pad.@54.1,34.166 pad.@54.1,62.916 pad.@54.2,61.091 pad.@54.2,62.016 pad.@54.3,57.766 pad.@54.4,56.941 pad.@54.05,32.441 pad.@54.8,32.391 pad.@54.35,66.541 pad.@54.075,33.341 pad.@54.275,58.591 pad.@54.675,63.466 pad.@54.825,33.341 pad.@54.875,34.166 pad.@55,62.566 pad.@55.25,57.141 pad.@55.55,32.366 pad.@55.65,33.341 pad.@55.575,63.491 pad.@55.675,34.166 pad.@55.825,62.541 pad.@56.025,57.116 pad.@56.35,63.491 pad.@56.45,34.191 pad.@56.425,32.316 pad.@56.425,33.316 pad.@57.2,33.341 pad.@57.2,34.141 pad.@57.225,32.316 Q3.E R8.2 R9.1 R48.2 R49.2 R50.2 U4.10 U4.11 U4.20 U4.40 | length 342.2
  TOP w0.25: U4.40@42.351,55.09 42.976,55.09 43.501,55.615 ; 47.651,53.533 47.651,52.94 50.851,49.74 50.851,42.14 pad.@51.001,41.99 ; 47.65,53.534 U4.10@47.65,54.291 ; U4.11@48.45,55.091 48.926,55.09 49.376,54.64 49.376,53.265 pad.@49.001,52.89 ; U4.20@48.45,59.591 49.001,59.59 49.376,59.965 49.376,68.99 ; pad.@50.325,69.941 49.376,68.99 ; pad.@50.325,69.941 49.376,68.992 49.376,68.99 ; pad.@53.451,56.64 pad.@53.676,56.64 ; 53.676,35.09 55.351,35.09 R50.2@55.875,35.616 ; pad.@53.675,56.716 pad.@53.676,56.64 ; pad.@54.401,56.94 pad.@54.401,56.64 ; R49.2@55.8,55.541 54.701,56.64 pad.@54.401,56.64 ; pad.@53.676,56.64 pad.@54.401,56.64
  TOP w0.3: pad.@52.6,36.966 53.277,36.966 55.326,36.965 55.876,36.415 R50.2@55.875,35.616 ; pad.@52.75,53.866 55.251,53.865 55.801,54.415 R49.2@55.8,55.541 ; pad.@54.35,66.541 54.35,66.44 55.426,66.44 55.926,65.94 R48.2@55.925,64.866 R48.2@55.925,64.866
  TOP w0.5: C31.2@41.1,44.341 41.1,45.216 pad.@41.05,45.266 41.101,45.317 C32.2@41.1,46.066
  TOP w1: Q3.E@42.207,32.591 42.207,31.509 ; R9.1@42.225,28.316 42.225,29.608 R8.2@42.225,30.616 42.207,30.634 42.207,31.509 ; pad.@46.15,31.166 46.101,31.215 42.208,31.215 42.208,31.508 42.207,31.509 ; pad.@53.451,55.54 pad.@53.751,55.54 ; pad.@53.751,55.765 pad.@53.751,55.54 ; 54.701,56.64 54.701,55.74 R49.2@54.501,55.54 ; R49.2@55.8,55.541 R49.2@54.501,55.54 ; pad.@53.751,55.54 R49.2@54.501,55.54
  TOP w2: pad.@53.25,63.641 pad.@53.101,63.79 ; pad.@53.25,63.641 pad.@53.101,63.49 ; pad.@53.276,61.915 pad.@53.101,61.915 ; pad.@53.276,62.815 pad.@53.101,62.815 ; pad.@53.451,55.54 53.451,56.64 53.451,56.716 pad.@53.451,57.69 ; pad.@53.601,57.69 pad.@53.451,57.69 ; pad.@53.975,64.041 53.976,64.815 ; pad.@54.075,33.341 53.765,33.496 53.676,33.54 ; pad.@54.1,34.166 53.676,34.165 ; pad.@54.1,62.916 pad.@53.101,62.915 ; pad.@54.2,62.016 54.201,61.565 ; pad.@54.3,57.766 pad.@54.301,58.015 ; pad.@54.676,63.465 pad.@55.251,63.465 ; pad.@54.8,32.391 pad.@54.851,32.365 ; pad.@54.825,33.341 pad.@55.251,33.34 ; pad.@54.876,34.165 pad.@55.251,34.165 ; pad.@55,62.566 pad.@55.251,62.565 ; R50.2@55.251,34.99 pad.@55.251,34.166 ; pad.@55.25,57.141 pad.@55.276,57.14 ; pad.@55.575,63.491 pad.@55.251,63.49 ; pad.@55.651,33.34 pad.@55.251,33.34 ; pad.@55.676,34.165 pad.@55.251,34.165 ; R50.2@55.875,35.616 55.851,35.64 53.676,35.64 53.676,35.09 53.676,34.165 ; R50.2@55.875,35.616 56.576,35.615 56.651,35.54 pad.@56.651,34.19 ; R48.2@56.376,64.815 R48.2@55.876,64.815 ; R49.2@56.401,55.565 56.113,55.854 55.438,56.528 55.276,56.69 55.276,57.116 pad.@55.276,57.14 ; pad.@56.426,33.315 pad.@56.651,33.315 ; pad.@56.451,34.19 pad.@56.651,34.19 ; pad.@53.101,61.915 53.101,62.016 pad.@53.101,62.815 ; pad.@53.101,61.915 53.101,61.565 54.1,61.565 54.201,61.565 ; pad.@53.101,62.815 pad.@53.101,62.915 ; pad.@53.101,62.915 pad.@53.101,63.49 ; pad.@53.101,63.49 pad.@53.101,63.79 ; pad.@53.101,63.79 53.101,64.815 53.976,64.815 ; pad.@53.451,57.69 53.451,57.766 53.451,58.015 53.6,58.015 pad.@54.301,58.015 ; 53.676,33.54 53.963,33.253 53.975,33.241 54.35,32.866 54.412,32.803 54.763,32.453 pad.@54.851,32.365 ; 53.676,33.54 53.676,34.165 ; 53.976,64.815 R48.2@55.876,64.815 ; 54.201,61.565 55.251,61.565 pad.@55.251,62.565 ; pad.@54.301,58.015 55.09,58.015 55.139,57.966 55.276,57.829 55.276,57.766 pad.@55.276,57.14 ; pad.@54.851,32.365 pad.@55.251,32.365 ; pad.@55.251,32.365 56.651,32.365 pad.@56.651,33.315 ; pad.@55.251,32.365 55.251,32.441 pad.@55.251,33.34 ; pad.@55.251,33.34 pad.@55.251,34.165 ; pad.@55.251,62.565 55.251,63.015 ; 55.251,63.015 56.038,63.803 56.426,64.19 56.426,64.865 R48.2@55.925,64.866 R48.2@55.876,64.815 ; 55.251,63.015 pad.@55.251,63.465 ; pad.@55.251,63.465 pad.@55.251,63.49 ; pad.@55.251,63.49 55.251,64.041 55.251,64.19 55.451,64.391 R48.2@55.876,64.815 ; pad.@56.651,33.315 56.651,34.166 pad.@56.651,34.19
  BOTTOM w0.127: 47.708,56.208 47.732,56.208 ; C37.1@53.325,66.601 C37.1@53.55,66.601
  BOTTOM w0.25: pad.@49.001,52.89 49.653,52.89 50.075,52.891 50.675,53.491 C41.1@51.751,53.491 ; pad.@50.325,69.941 50.95,69.941 51.675,69.216 51.675,67.266 52.339,66.601 53.55,66.601 53.55,66.441 C37.1@53.55,65.966 ; 51,41.337 51,38.841 52.015,37.827 52.549,37.827 C42.1@52.549,37.978 ; 51.001,41.338 pad.@51.001,41.99 ; C41.1@51.751,53.503 C41.1@51.751,53.491 ; C41.1@52.15,53.491 C41.1@51.751,53.491 ; pad.@52.875,55.891 53.125,55.891 53.3,55.716 ; pad.@53.575,55.716 pad.@53.75,55.716 ; pad.@53.75,55.766 pad.@53.75,55.716 ; 54.825,55.716 pad.@53.75,55.716
  BOTTOM w0.3: C41.1@52.125,53.866 pad.@52.75,53.866 ; C42.1@52.549,37.978 52.585,37.835 52.6,37.777 pad.@52.6,36.966 ; C37.1@53.55,66.441 pad.@54.25,66.441 ; pad.@54.25,66.441 54.35,66.441 pad.@54.35,66.541 pad.@54.25,66.441
  BOTTOM w0.5: C41.1@51.75,53.505 52.003,53.758 52.017,53.758 C41.1@52.125,53.866 ; C37.1@53.485,66.441 C37.1@53.55,66.441
  BOTTOM w2: pad.@46.225,30.116 53.3,30.116 ; pad.@46.575,31.591 53.3,31.591 ; 47.175,34.241 47.175,36.366 ; 48.275,39.641 47.825,40.091 47.825,37.866 48.475,37.866 49.125,37.216 ; 49.125,39.816 49.125,37.216 ; C1.2@52.775,28.441 C1.2@52.775,28.641 ; pad.@53.275,61.916 pad.@53.3,61.916 ; pad.@53.275,62.816 pad.@53.3,62.816 ; pad.@53.325,61.041 pad.@53.3,61.041 ; pad.@53.575,58.591 pad.@53.3,58.591 ; pad.@53.6,57.691 pad.@53.3,57.691 ; pad.@53.675,56.716 pad.@53.3,56.716 ; pad.@54.05,32.441 53.3,32.441 ; pad.@54.075,33.341 54.8,33.341 pad.@54.825,33.341 ; pad.@54.1,34.166 pad.@54.825,34.166 ; pad.@54.1,62.916 pad.@54.825,62.916 ; pad.@54.2,61.091 54.825,61.091 ; pad.@54.2,62.016 54.825,62.016 ; pad.@54.275,58.591 54.825,58.591 ; pad.@54.3,57.766 54.825,57.766 ; pad.@54.4,56.941 54.825,56.941 ; pad.@54.675,63.466 pad.@54.825,63.466 ; pad.@54.8,32.391 pad.@54.825,32.391 ; 54.825,29.966 pad.@54.825,32.366 ; pad.@54.875,34.166 pad.@54.825,34.166 ; pad.@55,62.566 pad.@54.825,62.566 ; pad.@55.25,57.141 54.825,57.141 ; pad.@55.575,63.491 pad.@54.825,63.491 ; pad.@55.65,33.341 pad.@56.4,33.341 ; pad.@55.675,34.166 pad.@56.4,34.166 ; pad.@55.825,62.541 56.4,62.541 ; pad.@56.025,57.116 pad.@56.4,57.116 ; 56.125,29.141 56.125,31.241 ; pad.@56.35,63.491 pad.@56.4,63.491 ; pad.@56.425,33.316 pad.@56.4,33.316 ; pad.@56.45,34.191 pad.@56.4,34.191 ; pad.@57.2,33.341 pad.@56.4,33.341 ; pad.@57.2,34.141 pad.@56.4,34.141 ; pad.@57.225,32.316 pad.@56.425,32.316 ; 58.575,28.791 56.4,30.966 pad.@56.4,32.227 ; 46.5,33.266 48.275,35.041 49.125,35.041 ; 46.5,33.266 52.25,33.266 ; 46.5,33.266 46.15,32.916 46.15,28.641 C1.2@52.775,28.641 ; 49.125,35.041 51.3,35.041 ; 49.125,35.041 49.125,37.216 ; 49.125,37.216 51.3,35.041 ; 51.3,35.041 51.3,34.216 52.25,33.266 ; 51.3,35.041 53.5,35.041 54.825,36.366 ; 52.25,33.266 53.3,33.266 53.3,32.441 ; C1.2@52.775,28.641 C1.2@52.825,28.641 ; C1.2@52.825,28.641 53.3,29.116 53.3,30.116 ; C1.2@52.825,28.641 C2.2@61.2,28.641 ; 53.3,30.116 53.3,31.591 ; 53.3,31.591 53.3,32.441 ; pad.@53.3,56.716 53.3,56.666 53.3,55.716 53.463,55.553 53.5,55.516 53.963,55.053 54.825,54.191 ; pad.@53.3,56.716 pad.@53.3,57.691 ; pad.@53.3,57.691 53.3,58.266 pad.@53.3,58.591 ; pad.@53.3,58.591 pad.@53.3,61.041 ; pad.@53.3,61.041 pad.@53.3,61.916 ; pad.@53.3,61.916 pad.@53.3,62.816 ; pad.@53.3,62.816 53.3,63.166 53.512,63.378 53.575,63.441 54.075,63.941 54.137,64.003 54.6,64.466 54.825,64.691 ; pad.@54.825,32.366 pad.@55.55,32.366 55.751,31.972 56.125,31.241 ; pad.@54.825,32.366 pad.@54.825,32.391 ; pad.@54.825,32.391 pad.@54.825,33.341 ; pad.@54.825,33.341 pad.@54.825,34.166 ; pad.@54.825,34.166 54.825,36.366 ; 54.825,36.366 54.825,54.191 ; 54.825,54.191 54.825,55.716 54.825,56.716 54.825,56.941 ; 54.825,56.941 54.825,57.141 ; 54.825,57.141 54.825,57.766 ; 54.825,57.766 54.825,58.591 ; 54.825,58.591 54.825,61.091 ; 54.825,61.091 54.825,62.016 ; 54.825,62.016 pad.@54.825,62.566 ; pad.@54.825,62.566 pad.@54.825,62.916 ; pad.@54.825,62.916 pad.@54.825,63.466 ; pad.@54.825,63.466 pad.@54.825,63.491 ; pad.@54.825,63.491 54.825,64.691 ; 54.825,64.691 56.4,64.691 ; 56.125,31.241 56.375,32.136 pad.@56.4,32.227 ; pad.@56.4,32.227 pad.@56.4,32.316 ; pad.@56.4,32.227 pad.@56.425,32.316 ; pad.@56.4,32.316 pad.@56.4,33.316 ; pad.@56.4,32.316 pad.@56.425,32.316 ; pad.@56.4,33.316 pad.@56.4,33.341 ; pad.@56.4,33.341 pad.@56.4,34.141 ; pad.@56.4,34.141 pad.@56.4,34.166 ; pad.@56.4,34.166 pad.@56.4,34.191 ; pad.@56.4,34.191 pad.@56.4,57.116 ; pad.@56.4,57.116 56.4,62.541 ; 56.4,62.541 pad.@56.4,63.491 ; pad.@56.4,63.491 56.4,64.691 ; 56.4,64.691 57.15,64.691 58.225,63.616 58.225,31.616 60.208,29.633 ; 60.208,29.633 C2.2@61.2,28.641 ; 60.208,29.633 C2.2@61.2,28.641 ; C2.2@61.2,28.641 C2.2@61.242,28.641 ; C2.2@61.2,28.641 C2.2@61.242,28.641 ; C2.2@61.242,28.641 C2.2@61.5,28.641 C2.2@61.242,28.641
PGND1: J6.2 J6.3 pad.@98.85,55.266 | length 12.4
  TOP w2.5: J6.2@85.575,56.991 J6.2@85.575,56.991 85.576,53.94 87.026,52.49 J6.3@88.125,52.491
  BOTTOM w2.5: J6.2@85.575,56.991 85.575,53.991 87.075,52.491 J6.3@88.125,52.491
REGOUT1: C28.1 U3.7 | length 3.4
  TOP w0.22: U3.7@34.025,52.391 34.026,50.89 34.826,50.09 34.826,49.44 C28.1@34.9,49.366
REGOUT2: C27.1 U3.6 | length 3.2
  TOP w0.22: C27.1@33.156,49.366 33.156,49.746 33.526,50.115 U3.6@33.525,52.391 ; C27.1@33.157,49.366 C27.1@33.225,49.366
RXD: P1.6 pad.@24.251,46.915 pad.@27.8,53.192 R27.2 U3.48 | length 13.9
  TOP w0.22: P1.6@21.187,47.526 23.64,47.526 pad.@24.251,46.915 ; pad.@27.8,53.192 27.782,53.21 27.782,53.221 28.651,54.09 U3.48@29.324,54.09
  BOTTOM w0.22: R27.2@23.875,46.216 23.875,46.541 24.007,46.672 24.008,46.672 pad.@24.251,46.915 24.795,47.459 24.795,47.46 25.95,48.616 25.95,51.342 pad.@27.8,53.192
RXD1: CON1.2 P2.6 pad.@87.2,31.441 | length 10.4
  TOP w0.3: pad.@87.276,31.517 87.201,31.442 87.201,35.699 P2.6@87.565,36.063
  BOTTOM w0.5: CON1.2@86.585,26.216 87.2,26.831 pad.@87.2,31.441
SB+: pad.@32.575,39.141 pad.@39.201,33.99 Q1.E R2.1 R4.2 SW1.1 | length 23.3
  TOP w0.5: R2.1@32.539,36.841 R2.1@32.539,36.841 32.54,36.001 33.026,35.515 38.326,35.515 39.201,34.64 pad.@39.201,33.99 ; pad.@32.575,39.141 33.651,39.14 SW1.1@33.65,39.366
  BOTTOM w0.5: R4.2@31.8,31.441 31.775,31.466 31.375,31.466 30.675,32.166 30.675,36.891 32.575,38.791 pad.@32.575,39.141 ; Q1.E@37.983,33.141 38.575,33.141 ; 38.55,32.916 39.2,32.916 39.2,33.366 ; 38.575,33.141 38.575,33.366 pad.@39.201,33.99 39.2,33.366 ; 38.575,33.141 38.975,33.141 39.2,33.366
SCL: P1.13 U3.24 | length 28.3
  TOP w0.22: P1.13@26.925,43.776 26.936,43.765 28.826,43.765 29.851,44.79 36.676,44.79 37.626,45.74 37.626,52.665 35.451,54.84 35.451,58.315 36.726,59.59 U3.24@38.225,59.591
SCL1: J5.1 P2.13 | length 13.8
  TOP w0.3: P2.13@91.315,41.741 91.315,42.079 92.351,43.115 92.351,45.39 93.276,46.315 98.426,46.315 99.551,47.44 J5.1@99.55,49.116
SCLK: P1.5 pad.@24.075,44.991 pad.@31.05,56.191 R43.1 U3.43 | length 28.9
  TOP w0.2: P1.5@21.187,46.276 22.79,46.276 pad.@24.075,44.991
  TOP w0.22: U3.43@29.326,56.59 30.651,56.59 30.72,56.521 ; 30.72,56.521 pad.@31.05,56.191
  BOTTOM w0.2: pad.@24.075,44.991 25.7,44.991 26.835,46.126 26.835,50.716 28.875,52.756 28.875,53.053 29.41,53.588 29.41,55.435
  BOTTOM w0.22: 29.41,55.435 30.165,56.191 pad.@31.05,56.191 31.225,56.016 33.025,56.016 34.775,57.766 38.225,57.766 R43.1@38.3,57.841
SCLK1: J4.5 P2.5 pad.@88.801,37.715 | length 12.9
  TOP w0.3: pad.@88.801,37.715 88.801,36.167 P2.5@88.815,36.153
  BOTTOM w0.3: pad.@88.801,37.715 89.55,38.466 89.55,47.061 J4.5@90.705,48.216
SDA: P1.12 U3.23 | length 28.6
  TOP w0.22: P1.12@26.925,42.526 26.936,42.515 28.276,42.515 30.121,44.36 36.946,44.36 38.076,45.49 38.076,52.865 35.901,55.04 35.901,58.065 36.926,59.091 U3.23@38.225,59.091
SDA1: J5.2 P2.12 pad.@92.575,40.466 | length 16.4
  TOP w0.3: P2.12@92.565,41.741 92.565,40.476 pad.@92.575,40.466
  BOTTOM w0.3: pad.@92.575,40.466 93.056,39.985 93.35,39.691 95.325,39.691 101.55,45.916 J5.2@101.55,49.116
SDO: pad.@31.951,56.94 pad.@43.776,64.565 R42.1 U3.42 U4.26 | length 30.3
  TOP w0.22: R42.1@23.475,57.391 R42.1@23.475,57.391 23.476,57.565 23.635,57.724 23.635,57.726 24.05,58.141 24.465,58.556 25.585,58.556 27.051,57.09 28.337,57.09 ; 28.338,57.091 U3.42@29.325,57.091 ; U3.42@29.326,57.09 31.801,57.09 pad.@31.951,56.94 ; pad.@43.776,64.565 44.576,63.765 44.576,63.29 45.151,62.715 U4.26@45.15,60.391
  BOTTOM w0.22: pad.@31.951,56.94 pad.@31.951,57.04 ; pad.@31.95,57.041 33.125,58.216 33.125,59.491 33.4,59.766 38.975,59.766 42.84,63.631 42.844,63.631 43.425,64.212 43.425,64.214 pad.@43.776,64.565 pad.@43.851,64.565
SREF1: pad.@34.451,41.742 R13.1 SW1.3 | length 5.1
  TOP w0.3: pad.@34.451,41.741 35.4,41.741 35.651,41.49 35.651,40.419 35.65,40.418 SW1.3@35.65,39.366
  BOTTOM w0.3: R13.1@33.775,43.016 33.8,42.991 33.8,42.166 34.224,41.742 pad.@34.451,41.742
SWCLK: P1.19 U3.3 | length 6.8
  TOP w0.22: P1.19@26.925,51.276 27.586,50.615 31.501,50.615 32.026,51.14 U3.3@32.026,52.39
SWCLK1: CON2.3 P2.19 | length 3.3
  TOP w0.3: P2.19@83.815,41.741 83.815,42.529 84.587,43.301 84.587,43.302 CON2.3@85.625,44.341
SWDIO: P1.20 U3.2 | length 6.4
  TOP w0.22: P1.20@27.025,52.526 27.235,52.315 30.301,52.315 30.605,52.62 30.605,53.268 30.788,53.45 31.264,53.45 31.289,53.425 31.306,53.425 31.526,53.205 U3.2@31.526,52.392
SWDIO1: CON2.2 P2.20 | length 2.7
  TOP w0.3: P2.20@82.565,41.841 82.551,41.855 82.551,43.807 CON2.2@83.085,44.341
SYNC1: pad.@30.975,59.266 R44.1 U3.40 | length 4.7
  TOP w0.22: U3.40@29.325,58.091 30.437,58.091 30.975,58.629 pad.@30.975,59.266
  BOTTOM w0.22: pad.@30.975,59.266 30.975,59.841 31.875,60.741 R44.1@32.25,60.741
SYNC2: P1.3 pad.@34.675,56.241 pad.@39.375,50.241 U3.25 | length 43.7
  TOP w0.22: P1.3@21.187,43.776 22.59,43.776 23.201,43.165 23.201,41.56 23.951,40.81 26.121,40.81 26.181,40.749 28.085,40.749 30.826,43.49 37.501,43.49 39.376,45.365 pad.@39.375,50.241 ; pad.@34.675,56.241 pad.@34.675,56.241 34.951,56.515 34.951,58.515 36.526,60.09 U3.25@36.525,61.291
  BOTTOM w0.22: pad.@34.675,56.241 35.575,57.141 37.25,57.141 38.1,56.291 38.1,51.516 pad.@39.375,50.241
SYNC2A: J4.6 P2.3 pad.@91.351,37.29 | length 14.6
  TOP w0.3: P2.3@91.315,36.003 91.326,36.014 91.326,37.265 pad.@91.351,37.29
  BOTTOM w0.3: pad.@91.35,37.291 91.35,41.366 92.3,42.316 92.3,47.271 ; J4.6@93.245,48.011 J4.6@93.245,48.216 ; 92.3,47.271 J4.6@93.245,48.216 ; 92.3,47.271 J4.6@93.245,48.216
